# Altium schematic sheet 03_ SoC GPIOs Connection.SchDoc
size 420 x 297 mm; SheetNumber: 3; SheetTotal: 4
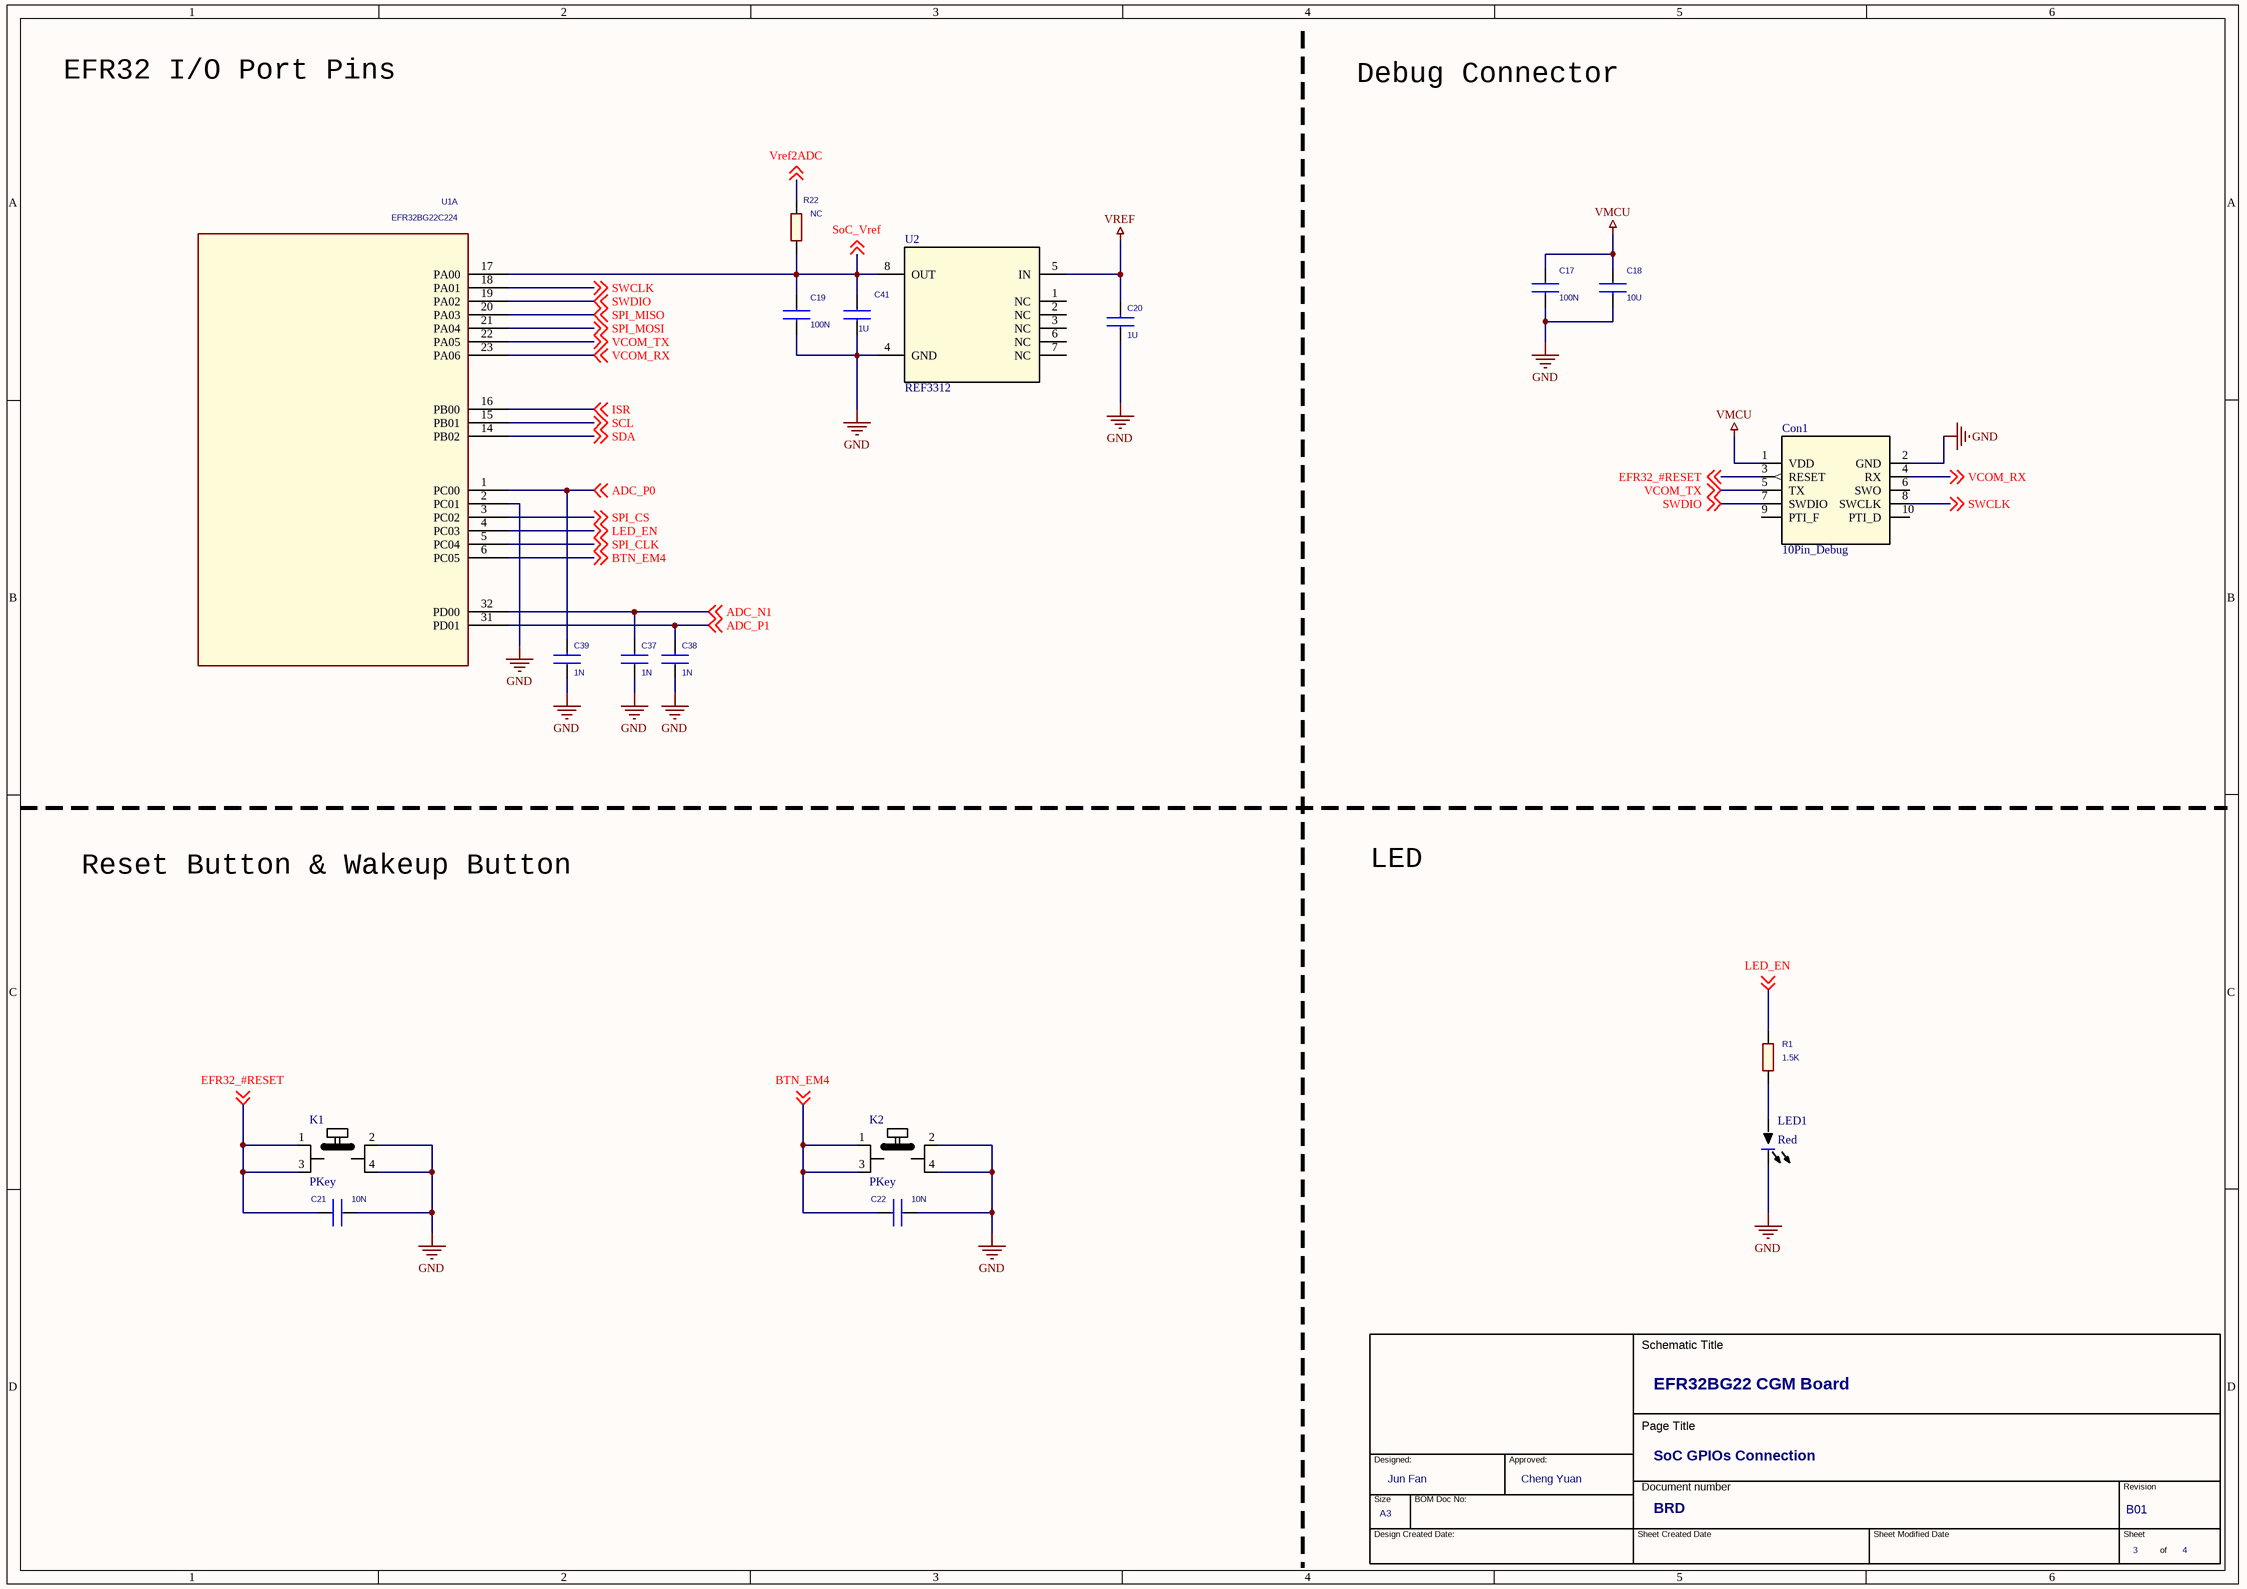
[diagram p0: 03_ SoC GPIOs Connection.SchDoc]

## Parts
*?  OrgAddr2: Cheng Yuan  OrgAddr1: Jun Fan  Page Count: 4  Page Number: 3  Doc: BRD  Title: EFR32BG22 CGM Board  RevCode: B01  Page Size: A3  Page Title: SoC GPIOs Connection  (hidden comment: TitleBlock_SiLabs_A3)  (graphical)
C17  100N  [C0201_L]
C18  10U  [C0603_L]
C19  100N  [C0201_L]
C20  1U  [C0402_L]
C21  10N  [C0201_L]
C22  10N  [C0201_L]
C37  1N  [C0201_L]
C38  1N  [C0201_L]
C39  1N  [C0201_L]
C41  1U  [C0402_L]
Con1  10Pin_Debug  [10Pin_Con]
K1  PKey  [PKey-P]
K2  PKey  [PKey-P]
LED1  LED  [LED_Red]  (value not drawn)
R1  1.5K  [R0402_L]
R22  NC  [R0402_L]
U1  EFR32BG22C224  [QFN32_M040_4.0X4.0_EP_SL]  (part A of 3)
U2  REF3312  [RSE0008A]

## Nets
GND: C17.2 C18.2 C19.2 C20.2 C21.2 C22.2 C37.2 C38.2 C39.2 C41.2 Con1.2(GND) K1.2(SIGNAL) K1.4(SIGNAL) K2.2(SIGNAL) K2.4(SIGNAL) LED1.1(Neg) U1.2(PC01) U2.4(GND)
VMCU: C17.1 C18.1 Con1.1(VDD)
VREF: C20.1 U2.5(IN)
ADC_N1: C37.1 U1.32(PD00) ; off-sheet ADC_N1
ADC_P0: C39.1 U1.1(PC00) ; off-sheet ADC_P0
ADC_P1: C38.1 U1.31(PD01) ; off-sheet ADC_P1
BTN_EM4: C22.1 K2.1(GND1) K2.3(GND4) U1.6(PC05) ; off-sheet BTN_EM4
EFR32_#RESET: C21.1 Con1.3(RESET) K1.1(GND1) K1.3(GND4) ; off-sheet EFR32_#RESET
ISR: U1.16(PB00) ; off-sheet ISR
LED_EN: R1.1 U1.4(PC03) ; off-sheet LED_EN
SCL: U1.15(PB01) ; off-sheet SCL
SDA: U1.14(PB02) ; off-sheet SDA
SoC_Vref: C19.1 C41.1 R22.1 U1.17(PA00) U2.8(OUT) ; off-sheet SoC_Vref
SPI_CLK: U1.5(PC04) ; off-sheet SPI_CLK
SPI_CS: U1.3(PC02) ; off-sheet SPI_CS
SPI_MISO: U1.20(PA03) ; off-sheet SPI_MISO
SPI_MOSI: U1.21(PA04) ; off-sheet SPI_MOSI
SWCLK: Con1.8(SWCLK) U1.18(PA01) ; off-sheet SWCLK
SWDIO: Con1.7(SWDIO) U1.19(PA02) ; off-sheet SWDIO
VCOM_RX: Con1.4(RX) U1.23(PA06) ; off-sheet VCOM_RX
VCOM_TX: Con1.5(TX) U1.22(PA05) ; off-sheet VCOM_TX
Vref2ADC: R22.2 ; off-sheet Vref2ADC
NetLED1_2: LED1.2(Positive) R1.2

Not connected (* = marked no-connect by the designer): Con1 6(SWO) 9(PTI_F) 10(PTI_D); U2 1(NC) 2(NC) 3(NC) 6(NC) 7(NC)

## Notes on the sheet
- EFR32 I/O Port Pins
- Debug Connector
- Reset Button & Wakeup Button
- LED

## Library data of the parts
*? = TitleBlock_SiLabs_A3: Cage Code: <Cage Code>
C17 C19-C22 C41 = C0201: Rating: 25V; Tolerance: 10%
C18 = C0603: Rating: 25V; Tolerance: 20%
C37-C39 = C0201: Rating: 10V; Tolerance: 10%
LED1 = LED_P: Mfg: Wurth Electronics; Mfg #: 150060YS75000
R1 R22 = RESISTOR: Tolerance: 5%
U1 = EFR32xG22_QFN32_2G4: MFG: Silicon Labs; MFG #: EFR32BG22C224F512IM32
U2 = REF3312AIRSET: No Description Available; PartNumber: REF3312AIRSER; Mfg: Texas Instruments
